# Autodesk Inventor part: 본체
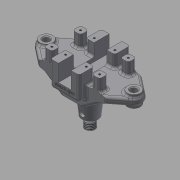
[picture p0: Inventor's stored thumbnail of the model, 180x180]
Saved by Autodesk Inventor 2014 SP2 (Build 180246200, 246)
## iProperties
Created: 2025-07
Part Number: 본체
Material: Generic
Document SubType Name: Modeling
Designer: Administrator
Density: 1 g/cm^3
Appearance: Default
Author: Administrator
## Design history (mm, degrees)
sketch "스케치8"
  geometry: L1 (-41.804, 23)-(41.804, 23); L2 (-41.804, 23)-(-61.157, 7.88); L3 (-61.157, -7.88)-(-41.804, -23); L4 (-41.804, -23)-(41.804, -23); L5 (41.804, -23)-(61.157, -7.88); L6 (-18, -13)-(18, -13); L7 (18, -13)-(18, -32.155); L8 (18, -32.155)-(-18, -32.155); L9 (-18, -32.155)-(-18, -13); L10 (-18, 31.845)-(18, 31.845); L11 (18, 31.845)-(18, 13); L12 (18, 13)-(-18, 13); L13 (-18, 13)-(-18, 31.845); L14 (25, -13)-(35, -13); L15 (35, -13)-(35, -23); L16 (35, -23)-(25, -23); L17 (25, -23)-(25, -13); L18 (-35, -23)-(-35, -13); L19 (-35, -13)-(-25, -13); L20 (-25, -13)-(-25, -23); L21 (-25, -23)-(-35, -23); L22 (25, 13)-(25, 23); L23 (25, 23)-(35, 23); L24 (35, 23)-(35, 13); L25 (35, 13)-(25, 13); L26 (-35, 13)-(-35, 23); L27 (-35, 23)-(-25, 23); L28 (-25, 23)-(-25, 13); L29 (-25, 13)-(-35, 13); L30 (41.804, 23)-(61.157, 7.88); A1 r 10 centre (55, 0) between (61.157, -7.88) and (61.157, 7.88); A2 r 10 centre (-55, 0) between (-61.157, 7.88) and (-61.157, -7.88); 11 further points
  constraints: 60 end point, 7 midpoint, 7 parallel, 5 horizontal, 4 horizontal alignment, 4 point on circle, 4 tangent, 4 vertical alignment, 3 equal length, 3 perpendicular, 2 centre point, 1 point on line, 1 vertical, 27 other
  dimensions: "d47" = 20 diameter of A2; "d48" = 20 diameter of A1; "d49" = 110 distance of A1.centre A2.centre; "d52" = 76 deg angle of L3 L2; "d53" = 64 distance between parallel lines of L8 L10; "d54" = 36 distance of L6.start L6.end; "d55" = 36 distance of L11.end L12.end; "d56" = 10 distance of L14.start L14.end; "d57" = 10 distance of L14.end L15.end; "d60" = 60 distance of L16.end L18.start; "d63" = 36 distance of L16.end L22.start; "d199" = 7 distance between parallel lines of L9 L20
extrude "돌출2" new body sketch "스케치8" distance "d66" = 16; taper "d67" = 0 deg
extrude "돌출3" join sketch "스케치8" distance "d68" = 16; taper "d69" = 0 deg
extrude "돌출4" join sketch "스케치8" distance "d70" = 25; taper "d71" = 0 deg
extrude "돌출5" join sketch "스케치8" distance "d72" = 15; taper "d73" = 0 deg
extrude "돌출6" join sketch "스케치8" distance "d74" = 25; taper "d75" = 0 deg
sketch "스케치9"
  geometry: L1 (16.804, -41)-(-66.804, -41) reference; L2 (-66.804, -41)-(-66.804, -16) reference; L3 (-66.804, -16)-(-60, -16) reference; L4 (-60, -16)-(-60, 0) reference; L5 (-60, 0)-(-50, 0) reference; L6 (-50, 0)-(-50, -16) reference; L7 (-50, -16)-(-43, -16) reference; L8 (-43, -31)-(-43, -16) reference; L9 (-7, -31)-(-43, -31) reference; L10 (-7, -16)-(-7, -31) reference; L11 (-7, 0)-(-7, -16) reference; L12 (-43, 0)-(-7, 0) reference; L13 (-43, -16)-(-43, 0) reference; L14 (16.804, -16)-(16.804, -41) reference; L15 (10, -16)-(16.804, -16) reference; L16 (10, 0)-(10, -16) reference; L17 (0, 0)-(10, 0) reference; L18 (0, -16)-(0, 0) reference; L19 (-7, -16)-(0, -16) reference; L20 (-41, -41)-(-9, -41); L21 (-9, -41)-(13.85, -25); L22 (-41, -41)-(-63.85, -25); L23 (-66.804, -16)-(-60, -16) reference; L24 (10, -16)-(16.804, -16) reference; L25 (10, 0)-(10, -16) reference; L26 (0, 0)-(10, 0) reference; L27 (0, -16)-(0, 0) reference; L28 (-7, -16)-(0, -16) reference; L29 (13.85, -25)-(37.491, -25); L30 (-9, -41)-(37.491, -41); L31 (-63.85, -25)-(-90.077, -25); L32 (-90.077, -25)-(-90.077, -41); L33 (-90.077, -41)-(-41, -41); L34 (16.804, -16)-(16.804, -41) reference; L35 (16.804, -41)-(-66.804, -41) reference; L36 (-66.804, -41)-(-66.804, -16) reference; L37 (37.491, -25)-(47.678, -25); L38 (47.678, -25)-(47.678, -41); L39 (47.678, -41)-(37.491, -41); L40 (-60, -16)-(-60, 0) reference; L41 (-60, 0)-(-50, 0) reference; L42 (-50, 0)-(-50, -16) reference; L43 (-50, -16)-(-43, -16) reference; L44 (-43, -31)-(-43, -16) reference; L45 (-7, -31)-(-43, -31) reference; L46 (-7, -16)-(-7, -31) reference; L47 (-7, 0)-(-7, -16) reference; L48 (-43, 0)-(-7, 0) reference; L49 (-43, -16)-(-43, 0) reference; 2 further points
  constraints: 22 end point, 4 parallel, 3 perpendicular, 2 point on line, 1 midpoint, 1 vertical alignment
  dimensions: "d76" = 32 distance of L20.start L20.end; "d79" = 35 deg angle of L20 L21; "d80" = 9 vertical distance of L14.start L21.end; "d81" = 35 deg angle of L20 L22; "d82" = 9 vertical distance of L2.end L22.end
extrude "돌출7" cut sketch "스케치9" stored distance "d83" = 25; taper "d84" = 0 deg
sketch "스케치10"
  geometry: L1 (-35, 23)-(-25, 23) reference; L2 (-25, 23)-(-25, 13) reference; L3 (-25, 13)-(-35, 13) reference; L4 (-35, 13)-(-35, 23) reference; L5 (25, 23)-(35, 23) reference; L6 (35, 23)-(35, 13) reference; L7 (35, 13)-(25, 13) reference; L8 (25, 13)-(25, 23) reference; L9 (18, -13)-(18, -32.155) reference; L10 (18, -32.155)-(-18, -32.155) reference; L11 (-18, -32.155)-(-18, -13) reference; L12 (-18, -13)-(18, -13) reference; L13 (18, 31.845)-(18, 13) reference; L14 (18, 13)-(-18, 13) reference; L15 (-18, 13)-(-18, 31.845) reference; L16 (-18, 31.845)-(18, 31.845) reference; L17 (-25, -13)-(-25, -23) reference; L18 (-25, -23)-(-35, -23) reference; L19 (-35, -23)-(-35, -13) reference; L20 (-35, -13)-(-25, -13) reference; L21 (35, -23)-(25, -23) reference; L22 (25, -23)-(25, -13) reference; L23 (25, -13)-(35, -13) reference; L24 (35, -13)-(35, -23) reference; L25 (-8, 31.845)-(8, 31.845); L26 (8, 31.845)-(8, -32.155); L27 (8, -32.155)-(-8, -32.155); L28 (-8, -32.155)-(-8, 31.845); 2 further points
  constraints: 8 end point, 2 parallel, 2 point on line, 1 horizontal, 1 midpoint, 1 perpendicular, 1 vertical alignment
  dimensions: "d85" = 16 distance of L25.start L25.end
extrude "돌출8" cut sketch "스케치10" distance "d86" = 21; taper "d87" = 0 deg
sketch "스케치11"
  geometry: L1 (18, -32.155)-(8, -32.155) reference; L2 (8, -32.155)-(8, -13) reference; L3 (25, -23)-(25, -13) reference; L4 (61.157, -7.88)-(41.804, -23) reference; L5 (41.804, 23)-(61.157, 7.88) reference; L6 (18, 23)-(18, 13) reference; L7 (8, 13)-(8, 31.845) reference; L8 (8, 31.845)-(18, 31.845) reference; L9 (18, 31.845)-(18, 23) reference; L10 (8, -13)-(8, 13) reference; L11 (35, -23)-(25, -23) reference; L12 (-41.804, -23)-(-61.157, -7.88) reference; L13 (-18, -23)-(-18, -13) reference; L14 (-18, -13)-(-8, -13) reference; L15 (-8, -13)-(-8, -32.155) reference; L16 (-8, -32.155)-(-18, -32.155) reference; L17 (-18, -32.155)-(-18, -23) reference; L18 (-18, 13)-(-18, 23) reference; L19 (-8, 31.845)-(-8, 13) reference; L20 (-18, 31.845)-(-8, 31.845) reference; L21 (-18, 23)-(-18, 31.845) reference; L22 (-8, 13)-(-8, -13) reference; L23 (41.804, -23)-(35, -23) reference; L24 (-41.804, 23)-(-35, 23) reference; L25 (25, -13)-(35, -13) reference; L26 (35, -13)-(35, -23) reference; L27 (18, 13)-(8, 13) reference; L28 (25, 23)-(35, 23) reference; L29 (25, 13)-(25, 23) reference; L30 (35, 13)-(25, 13) reference; L31 (35, 23)-(35, 13) reference; L32 (-8, 13)-(-18, 13) reference; L33 (25, -23)-(18, -23) reference; L34 (18, -13)-(18, -23) reference; L35 (18, -23)-(18, -32.155) reference; L36 (8, -13)-(18, -13) reference; L37 (35, 23)-(41.804, 23) reference; L38 (18, 23)-(25, 23) reference; L39 (-25, -13)-(-25, -23) reference; L40 (-18, -23)-(-25, -23) reference; L41 (-35, -13)-(-25, -13) reference; L42 (-35, -23)-(-35, -13) reference; L43 (-25, -23)-(-35, -23) reference; L44 (-35, -23)-(-41.804, -23) reference; L45 (-35, 23)-(-25, 23) reference; L46 (-25, 23)-(-18, 23) reference; L47 (-35, 13)-(-35, 23) reference; L48 (-25, 13)-(-35, 13) reference; L49 (-25, 23)-(-25, 13) reference; L50 (-61.157, 7.88)-(-41.804, 23) reference; C1 r 8 at (-55, 0); C2 r 8 at (55, 0); A1 r 10 centre (55, 0) between (61.157, -7.88) and (61.157, 7.88) reference; A2 r 10 centre (-55, 0) between (-61.157, 7.88) and (-61.157, -7.88) reference; 1 further point
  constraints: 2 centre point, 1 coincident
  dimensions: "d97" = 16 diameter of C1; "d98" = 16 diameter of C2; "d99" = 110 distance of C1.centre C2.centre
  node "절단 모서리 투영7"
extrude "돌출9" join sketch "스케치11" distance "d100" = 3; taper "d101" = 0 deg
extrude "돌출10" join sketch "스케치11" distance "d102" = 12; taper "d103" = 0 deg
sketch "스케치12"
  geometry: L1 (-7, -31)-(-43, -31) reference; L2 (-43, -31)-(-43, -16) reference; L3 (-50, -16)-(-43, -16) reference; L4 (-50, 0)-(-50, -16) reference; L5 (-60, 0)-(-50, 0) reference; L6 (-60, -16)-(-60, 0) reference; L7 (-66.804, -16)-(-60, -16) reference; L8 (-66.804, -25)-(-66.804, -16) reference; L9 (-63.85, -25)-(-66.804, -25) reference; L10 (-41, -41)-(-63.85, -25) reference; L11 (-9, -41)-(-41, -41) reference; L12 (13.85, -25)-(-9, -41) reference; L13 (16.804, -25)-(13.85, -25) reference; L14 (16.804, -16)-(16.804, -25) reference; L15 (10, -16)-(16.804, -16) reference; L16 (10, 0)-(10, -16) reference; L17 (0, 0)-(10, 0) reference; L18 (0, -16)-(0, 0) reference; L19 (-7, -16)-(0, -16) reference; L20 (-7, 0)-(-7, -16) reference; L21 (-17, 0)-(-7, 0) reference; L22 (-17, -21)-(-17, 0) reference; L23 (-33, -21)-(-17, -21) reference; L24 (-33, 0)-(-33, -21) reference; L25 (-43, 0)-(-33, 0) reference; L26 (-43, -16)-(-43, 0) reference; L27 (-7, -16)-(-7, -31) reference; 1 further point
  node "절단 모서리 투영8"
fillet "모깎기10" dims "d106" = 3
fillet "모깎기11" dims "d107" = 3
fillet "모깎기12" dims "d108" = 3
fillet "모깎기13" dims "d109" = 3
fillet "모깎기14" dims "d110" = 3
fillet "모깎기15" dims "d111" = 3
fillet "모깎기16" dims "d112" = 3
fillet "모깎기17" dims "d113" = 3
fillet "모깎기18" dims "d114" = 3
fillet "모깎기19" dims "d115" = 3
fillet "모깎기21" dims "d117" = 3
sketch "스케치13"
  geometry: L1 (-28, -23)-(-32, -23) reference; L2 (-35, -20)-(-35, -16) reference; L3 (-32, -13)-(-28, -13) reference; L4 (-25, -16)-(-25, -20) reference; L5 (-15, 31.845)-(-8, 31.845) reference; L6 (-8, 31.845)-(-8, 13) reference; L7 (-8, 13)-(-18, 13) reference; L8 (-18, 13)-(-18, 28.845) reference; L9 (18, 28.845)-(18, 16) reference; L10 (15, 13)-(8, 13) reference; L11 (8, 13)-(8, 31.845) reference; L12 (8, 31.845)-(15, 31.845) reference; L13 (28, -13)-(32, -13) reference; L14 (35, -16)-(35, -20) reference; L15 (25, -20)-(25, -16) reference; L16 (25, 16)-(25, 20) reference; L17 (35, 20)-(35, 16) reference; L18 (32, 13)-(28, 13) reference; L19 (-35, 16)-(-35, 20) reference; L20 (-25, 20)-(-25, 16) reference; L21 (-28, 13)-(-32, 13) reference; L22 (-8, -13)-(-8, -32.155) reference; L23 (-8, -32.155)-(-18, -32.155) reference; L24 (-18, -32.155)-(-18, -13) reference; L25 (-18, -13)-(-8, -13) reference; L26 (8, -32.155)-(8, -13) reference; L27 (8, -13)-(15, -13) reference; L28 (18, -16)-(18, -29.155) reference; L29 (15, -32.155)-(8, -32.155) reference; L30 (32, -23)-(28, -23) reference; L31 (28, 23)-(32, 23) reference; L32 (-32, 23)-(-28, 23) reference; C1 r 4 at (-55, 0); C2 r 4 at (55, 0); A1 r 8 centre (55, 0) between (53.271, 7.811) and (53.271, -7.811) reference; A2 r 8 centre (55, 0) between (53.271, -7.811) and (53.271, 7.811) reference; A3 r 3 centre (-32, -20) between (-34.693, -21.323) and (-32.632, -22.933) reference; A4 r 3 centre (-32, -20) between (-32.632, -22.933) and (-32, -23) reference; A5 r 3 centre (-32, -20) between (-35, -20) and (-34.693, -21.323) reference; A6 r 3 centre (-32, -16) between (-32, -13) and (-35, -16) reference; A7 r 3 centre (-28, -16) between (-25, -16) and (-28, -13) reference; A8 r 3 centre (-15, 28.845) between (-15, 31.845) and (-18, 28.845) reference; A9 r 3 centre (15, 16) between (15, 13) and (18, 16) reference; A10 r 3 centre (15, 28.845) between (18, 28.845) and (15, 31.845) reference; A11 r 3 centre (28, -16) between (28, -13) and (25, -16) reference; A12 r 3 centre (32, -16) between (35, -16) and (32, -13) reference; A13 r 3 centre (28, 16) between (25, 16) and (28, 13) reference; A14 r 3 centre (32, 16) between (32, 13) and (35, 16) reference; A15 r 3 centre (-32, 16) between (-35, 16) and (-32, 13) reference; A16 r 3 centre (-28, 16) between (-28, 13) and (-25, 16) reference; A17 r 3 centre (15, -16) between (18, -16) and (15, -13) reference; A18 r 3 centre (15, -29.155) between (15, -32.155) and (18, -29.155) reference; A19 r 8 centre (-55, 0) between (-53.271, -7.811) and (-53.271, 7.811) reference; A20 r 8 centre (-55, 0) between (-53.271, 7.811) and (-53.271, -7.811) reference; A21 r 3 centre (32, -20) between (34.693, -21.323) and (35, -20) reference; A22 r 3 centre (32, -20) between (32, -23) and (32.632, -22.933) reference; A23 r 3 centre (32, -20) between (32.632, -22.933) and (34.693, -21.323) reference; A24 r 3 centre (28, -20) between (25, -20) and (28, -23) reference; A25 r 3 centre (-28, -20) between (-28, -23) and (-25, -20) reference; A26 r 3 centre (28, 20) between (28, 23) and (25, 20) reference; A27 r 3 centre (32, 20) between (34.693, 21.323) and (32.632, 22.933) reference; A28 r 3 centre (32, 20) between (32.632, 22.933) and (32, 23) reference; A29 r 3 centre (32, 20) between (35, 20) and (34.693, 21.323) reference; A30 r 3 centre (-32, 20) between (-34.693, 21.323) and (-35, 20) reference; A31 r 3 centre (-32, 20) between (-32, 23) and (-32.632, 22.933) reference; A32 r 3 centre (-32, 20) between (-32.632, 22.933) and (-34.693, 21.323) reference; A33 r 3 centre (-28, 20) between (-25, 20) and (-28, 23) reference; 2 further points
  constraints: 2 centre point, 1 coincident
  dimensions: "d118" = 8 diameter of C1; "d119" = 8 diameter of C2
hole "구멍1" sketch "스케치13" at (55, 0), (-55, 0) diameter "d120" = 8; stored, may be unused: countersink angle "d124" = 82 deg, drill point angle "d126" = 0 deg; dims "d121" = 6, "d122" = 3.023, "d123" = 2, "d125" = 8
chamfer "모따기1" distance "d127" = 1; stored, may be unused: second distance "d128" = 2, angle "d129" = 45 deg
chamfer "모따기2" distance "d130" = 1; stored, may be unused: second distance "d131" = 2, angle "d132" = 45 deg
chamfer "모따기3" distance "d133" = 1; stored, may be unused: second distance "d134" = 2, angle "d135" = 45 deg
chamfer "모따기4" distance "d136" = 1; stored, may be unused: second distance "d137" = 2, angle "d138" = 45 deg
sketch "스케치14"
  geometry: L1 (-15, 31.845)-(-8, 31.845) reference; L2 (-8, 31.845)-(-8, 13) reference; L3 (-8, 13)-(-18, 13) reference; L4 (-18, 13)-(-18, 28.845) reference; L5 (18, 28.845)-(18, 16) reference; L6 (15, 13)-(8, 13) reference; L7 (8, 13)-(8, 31.845) reference; L8 (8, 31.845)-(15, 31.845) reference; L9 (35, -16)-(35, -20) reference; L10 (32, -23)-(28, -23) reference; L11 (25, -20)-(25, -16) reference; L12 (28, -13)-(32, -13) reference; L13 (32, 13)-(28, 13) reference; L14 (25, 16)-(25, 20) reference; L15 (28, 23)-(32, 23) reference; L16 (35, 20)-(35, 16) reference; L17 (-25, -16)-(-25, -20) reference; L18 (-28, -23)-(-32, -23) reference; L19 (-35, -20)-(-35, -16) reference; L20 (-32, -13)-(-28, -13) reference; L21 (-28, 13)-(-32, 13) reference; L22 (-35, 16)-(-35, 20) reference; L23 (-32, 23)-(-28, 23) reference; L24 (-25, 20)-(-25, 16) reference; L25 (-8, -13)-(-8, -32.155) reference; L26 (-8, -32.155)-(-18, -32.155) reference; L27 (-18, -32.155)-(-18, -13) reference; L28 (-18, -13)-(-8, -13) reference; L29 (8, -32.155)-(8, -13) reference; L30 (8, -13)-(15, -13) reference; L31 (18, -16)-(18, -29.155) reference; L32 (15, -32.155)-(8, -32.155) reference; A1 r 3 centre (-15, 28.845) between (-15, 31.845) and (-18, 28.845) reference; A2 r 3 centre (15, 16) between (15, 13) and (18, 16) reference; A3 r 3 centre (15, 28.845) between (18, 28.845) and (15, 31.845) reference; A4 r 3 centre (32, -16) between (35, -16) and (32, -13) reference; A5 r 3 centre (32, -20) between (32, -23) and (35, -20) reference; A6 r 3 centre (28, -20) between (25, -20) and (28, -23) reference; A7 r 3 centre (28, -16) between (28, -13) and (25, -16) reference; A8 r 3 centre (32, 16) between (32, 13) and (35, 16) reference; A9 r 3 centre (28, 16) between (25, 16) and (28, 13) reference; A10 r 3 centre (28, 20) between (28, 23) and (25, 20) reference; A11 r 3 centre (32, 20) between (35, 20) and (32, 23) reference; A12 r 3 centre (-28, -16) between (-25, -16) and (-28, -13) reference; A13 r 3 centre (-28, -20) between (-28, -23) and (-25, -20) reference; A14 r 3 centre (-32, -20) between (-35, -20) and (-32, -23) reference; A15 r 3 centre (-32, -16) between (-32, -13) and (-35, -16) reference; A16 r 3 centre (-28, 16) between (-28, 13) and (-25, 16) reference; A17 r 3 centre (-32, 16) between (-35, 16) and (-32, 13) reference; A18 r 3 centre (-32, 20) between (-32, 23) and (-35, 20) reference; A19 r 3 centre (-28, 20) between (-25, 20) and (-28, 23) reference; A20 r 3 centre (15, -16) between (18, -16) and (15, -13) reference; A21 r 3 centre (15, -29.155) between (15, -32.155) and (18, -29.155) reference; 9 further points
  dimensions: "d139" = 26 distance of point (-13.26, 18) point (12.74, 18); "d140" = 5 distance from line of L15 point (30, 18); "d141" = 5 distance from line of L14 point (30, 18); "d142" = 5 distance from line of L9 point (30, -18); "d143" = 5 distance from line of L12 point (30, -18); "d144" = 26 distance of point (-13.26, -18) point (12.74, -18); "d145" = 5 distance from line of L20 point (-30, -18); "d146" = 5 distance from line of L17 point (-30, -18); "d147" = 5 distance from line of L24 point (-30, 18); "d148" = 5 distance from line of L21 point (-30, 18); "d149" = 36 distance of point (12.74, 18) point (12.74, -18); "d150" = 5 distance from line of L30 point (12.74, -18)
hole "구멍2" sketch "스케치14" at (-30, 18), (30, 18), (12.74, 18), (-13.26, 18), (-13.26, -18), (12.74, -18), (30, -18), (-30, -18) diameter "d151" = 2.459; stored, may be unused: countersink angle "d155" = 90 deg, drill point angle "d157" = 118 deg; dims "d152" = 6, "d153" = 6.3, "d154" = 2, "d156" = 8
fillet "모깎기22" dims "d158" = 3
fillet "모깎기23" dims "d159" = 3
node "작업 평면3"
sketch "스케치15"
  geometry: L1 (-65, 3)-(-65, 6) reference; L2 (-63, 10.472)-(-63, 12) reference; L3 (-63, 12)-(-60, 12) reference; L4 (-60, 12)-(-59, 11) reference; L5 (-59, 11)-(-59, -2) reference; L6 (-59, -2)-(-60, -3) reference; L7 (-60, -3)-(-63, -3) reference; L8 (-63, -3)-(-63, -1.472) reference; L9 (63, -1.472)-(63, -3) reference; L10 (63, -3)-(60, -3) reference; L11 (60, -3)-(59, -2) reference; L12 (59, -2)-(59, 11) reference; L13 (59, 11)-(60, 12) reference; L14 (60, 12)-(63, 12) reference; L15 (63, 12)-(63, 10.472) reference; L16 (65, 6)-(65, 3) reference; L17 (-16, 25)-(16, 25) reference; L18 (16, 25)-(38.076, 9.543) reference; L19 (39.796, 9)-(44, 9) reference; L20 (47, 12)-(50, 12) reference; L21 (50, 12)-(51, 11) reference; L22 (51, 11)-(51, -2) reference; L23 (51, -2)-(50, -3) reference; L24 (50, -3)-(47, -3) reference; L25 (44, 0)-(8, 0) reference; L26 (8, 0)-(8, 5) reference; L27 (8, 5)-(-8, 5) reference; L28 (-8, 5)-(-8, 0) reference; L29 (-8, 0)-(-44, 0) reference; L30 (-47, -3)-(-50, -3) reference; L31 (-50, -3)-(-51, -2) reference; L32 (-51, -2)-(-51, 11) reference; L33 (-51, 11)-(-50, 12) reference; L34 (-50, 12)-(-47, 12) reference; L35 (-44, 9)-(-39.796, 9) reference; L36 (-38.076, 9.543)-(-16, 25) reference; L37 (0, 25)-(0, 66); L38 (-12.5, 25)-(-12.5, 29); L39 (-12.5, 29)-(-10, 52); L40 (-10, 52)-(0, 52); L41 (-4.7, 55)-(0, 55); L42 (-4.7, 55)-(-4.7, 52); L43 (-65, 3)-(-65, 6) reference; L44 (-63, 10.472)-(-63, 12) reference; L45 (-63, 12)-(-60, 12) reference; L46 (-60, 12)-(-59, 11) reference; L47 (-59, 11)-(-59, -2) reference; L48 (-59, -2)-(-60, -3) reference; L49 (-60, -3)-(-63, -3) reference; L50 (-63, -3)-(-63, -1.472) reference; L51 (63, -1.472)-(63, -3) reference; L52 (63, -3)-(60, -3) reference; L53 (60, -3)-(59, -2) reference; L54 (59, -2)-(59, 11) reference; L55 (59, 11)-(60, 12) reference; L56 (60, 12)-(63, 12) reference; L57 (63, 12)-(63, 10.472) reference; L58 (65, 6)-(65, 3) reference; L59 (-16, 25)-(16, 25) reference; L60 (16, 25)-(38.076, 9.543) reference; L61 (39.796, 9)-(44, 9) reference; L62 (47, 12)-(50, 12) reference; L63 (50, 12)-(51, 11) reference; L64 (51, 11)-(51, -2) reference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; A1 r 3 centre (-66, -1.472) between (-63, -1.472) and (-64, 0.764) reference; A2 r 3 centre (-62, 3) between (-65, 3) and (-64, 0.764) reference; A3 r 3 centre (-62, 6) between (-64, 8.236) and (-65, 6) reference; A4 r 3 centre (-66, 10.472) between (-64, 8.236) and (-63, 10.472) reference; A5 r 3 centre (66, -1.472) between (64, 0.764) and (63, -1.472) reference; A6 r 3 centre (66, 10.472) between (63, 10.472) and (64, 8.236) reference; A7 r 3 centre (62, 6) between (65, 6) and (64, 8.236) reference; A8 r 3 centre (62, 3) between (64, 0.764) and (65, 3) reference; A9 r 3 centre (39.796, 12) between (38.076, 9.543) and (39.796, 9) reference; A10 r 3 centre (44, 12) between (44, 9) and (47, 12) reference; A11 r 3 centre (44, -3) between (47, -3) and (44, 0) reference; A12 r 3 centre (-44, -3) between (-44, 0) and (-47, -3) reference; A13 r 3 centre (-44, 12) between (-47, 12) and (-44, 9) reference; A14 r 3 centre (-39.796, 12) between (-39.796, 9) and (-38.076, 9.543) reference; A15 r 3 centre (-66, -1.472) between (-63, -1.472) and (-64, 0.764) reference; A16 r 3 centre (-62, 3) between (-65, 3) and (-64, 0.764) reference; A17 r 3 centre (-62, 6) between (-64, 8.236) and (-65, 6) reference; A18 r 3 centre (-66, 10.472) between (-64, 8.236) and (-63, 10.472) reference; A19 r 3 centre (66, -1.472) between (64, 0.764) and (63, -1.472) reference; A20 r 3 centre (66, 10.472) between (63, 10.472) and (64, 8.236) reference; A21 r 3 centre (62, 6) between (65, 6) and (64, 8.236) reference; A22 r 3 centre (62, 3) between (64, 0.764) and (65, 3) reference; A23 r 3 centre (39.796, 12) between (38.076, 9.543) and (39.796, 9) reference; A24 r 3 centre (44, 12) between (44, 9) and (47, 12) reference; A25 r 3 centre (44, -3) between (47, -3) and (44, 0) reference; A26 r 3 centre (-44, -3) between (-44, 0) and (-47, -3) reference; A27 r 3 centre (-44, 12) between (-47, 12) and (-44, 9) reference; A28 r 3 centre (-39.796, 12) between (-39.796, 9) and (-38.076, 9.543) reference; 2 further points
  constraints: 20 end point, 5 perpendicular, 4 point on line, 3 parallel, 2 midpoint
  dimensions: "d163" = 4 distance of L38.start L38.end; "d166" = 25 diameter of L38 L37; "d171" = 20 diameter of L39.end L37; "d172" = 9.4 diameter of L42 L37; "d175" = 23 vertical distance of L39.end L38.end; "d176" = 3 distance of L41.start L42.end; "d177" = 12 diameter of L79 L37; "d178" = 30 deg angle of L79 L80; "d181" = 41 distance of L37.end L37.start; "d182" = 30 deg angle of L82 L81; "d183" = 9.4 diameter of L81.end L37
  node "절단 모서리 투영11"
  node "절단 모서리 투영13"
revolve "회전3" stored, may be unused: angle "d168" = 180 deg
revolve "회전4" stored, may be unused: angle "d184" = 180 deg
feature "스레드1" dims "d185" = 10, "d186" = 0
sketch "스케치17"
  geometry: L1 (16, 21)-(23, 21) reference; 2 further points
  constraints: 1 vertical alignment, 1 other
  dimensions: "d187" = 24 distance from line of point (8, -3) L1
feature "엠보싱1" sketch "스케치17" dims "d47" = 20, "d48" = 20, "d49" = 110, "d52" = 76 deg, "d53" = 64, "d54" = 36, "d55" = 36, "d56" = 10, "d57" = 10, "d60" = 60, "d63" = 36, "d188" = 0.5, "d189" = 0, "d199" = 7
node "작업 평면6"
  node "작업 평면5"
sketch "스케치18"
  geometry: L1 (45.304, 12.102)-(45.304, 22.822); L2 (38.304, 12.102)-(38.304, 22.822); L3 (25.804, 1.105)-(57.804, 1.105) reference; L4 (57.804, 1.105)-(79.88, -14.468) reference; L5 (81.6, -15.015)-(87.827, -15.015) reference; L6 (92.228, -18.038)-(91.757, -21.06) reference; L7 (86.412, -24.083)-(79.804, -24.083) reference; L8 (76.804, -27.105)-(76.804, -40.203) reference; L9 (76.804, -40.203)-(72.564, -40.203) reference; L10 (71.044, -40.203)-(66.804, -40.203) reference; L11 (66.804, -40.203)-(66.804, -27.105) reference; L12 (63.804, -24.083)-(59.804, -24.083) reference; L13 (59.804, -24.083)-(59.804, -40.203) reference; L14 (59.804, -40.203)-(55.304, -40.203) reference; L15 (53.784, -40.203)-(49.804, -40.203) reference; L16 (49.804, -40.203)-(49.804, -19.045) reference; L17 (49.804, -19.045)-(33.804, -19.045) reference; L18 (33.804, -19.045)-(33.804, -40.203) reference; L19 (33.804, -40.203)-(29.304, -40.203) reference; L20 (27.784, -40.203)-(23.804, -40.203) reference; L21 (23.804, -40.203)-(23.804, -24.083) reference; L22 (23.804, -24.083)-(19.804, -24.083) reference; L23 (16.804, -27.105)-(16.804, -40.203) reference; L24 (16.804, -40.203)-(12.564, -40.203) reference; L25 (11.044, -40.203)-(6.804, -40.203) reference; L26 (6.804, -40.203)-(6.804, -27.105) reference; L27 (3.804, -24.083)-(-2.804, -24.083) reference; L28 (-4.219, -15.015)-(2.008, -15.015) reference; L29 (3.728, -14.468)-(25.804, 1.105) reference; L30 (-8.149, -21.06)-(-8.62, -18.038) reference; A1 r 3.5 centre (41.804, 12.102) between (38.304, 12.102) and (45.304, 12.102); A2 r 3.5 centre (41.804, 22.102) between (45.304, 22.102) and (38.304, 22.102); 28 further points; 19 other entities
  constraints: 4 end point, 4 horizontal alignment, 4 point on circle, 3 tangent, 2 centre point, 2 point on line, 1 parallel, 1 vertical, 1 vertical alignment, 19 other
  dimensions: "d192" = 7 diameter of A1; "d194" = 10 distance of A1.centre A2.centre; "d195" = 7.5 distance of point (41.804, 29.602) A2.centre
extrude "돌출11" cut sketch "스케치18" distance "d196" = 4; taper "d197" = 0 deg
fillet "모깎기24" dims "d201" = 3
node "솔리드4"
node "작업 평면4"
node "절단 모서리 투영4"
node "절단 모서리 투영5"
node "절단 모서리 투영6"
node "절단 모서리 투영9"
node "절단 모서리 투영10"
node "절단 모서리 투영15"
other parameters: "d161" = 90 deg, "d190" = -7 deg, "d191" = -9
